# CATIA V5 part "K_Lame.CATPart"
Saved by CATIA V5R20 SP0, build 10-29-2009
Part number: Lame
Bounding box of the stored display mesh (mm): x -10.5 to -4.5, y 4 to 196, z -27 to -7
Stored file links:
  G:\Khaled_CFAO_2011\SIL\SIL_GR1\mneves\Khaled\CAD_CATIA_Modifie\K_Lame.CATPart
  G:\Khaled_CFAO_2011\SIL\SIL_GR1\mneves\Khaled\CAD_CATIA_Modifie\K_AssPince_A_Bois.CATProduct
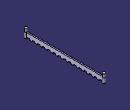
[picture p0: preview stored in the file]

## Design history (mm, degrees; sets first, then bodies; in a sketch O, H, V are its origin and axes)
External parameters (linked from other documents)
  External.Encombrement_Lame = 12 mm
  External.Epaisseur_Cloison = 3 mm
  External.Distance_Inter_Pivot = 200 mm
  External.Distance_Inter_Pivot.1 = 200 mm
  External.Encombrement_Lame.1 = 12 mm
Set1
  Plane1: linked copy from another document
  Point1: linked copy from another document
  Point2: linked copy from another document
  Line1: linked copy from another document
Body1 (main body)
  Sketch1 on Plane1, origin (0, 0, -27), H (1, 0, 0), V (0, 1, 0)
    arc A1 centre (-7.5, 193) radius 3 from (-6, 190.4019) to (-9, 190.4019) ccw
    point P1 (-7.5, 193)
    reference projected point E1 (-7.5, 193) from Point1
    arc A2 centre (-7.5, 7) radius 3 from (-9, 9.5981) to (-6, 9.5981) ccw
    point P2 (-7.5, 7)
    reference projected point E2 (-7.5, 7) from Point2
    line L1 (-6, 190.4019) -> (-6, 9.5981)
    line L2 (-9, 9.5981) -> (-9, 190.4019)
    reference projected line E3 (-7.5, 7) -> (-7.5, 193) from Line1
    reference projected line E4 (-7.5, 7) -> (-7.5, 193) from Line1
    radius A1 = 3 {= External.Encombrement_Lame /4}
    radius A2 = 3 {= External.Encombrement_Lame /4}
    distance E3 L2 = 1.5 {= External.Encombrement_Lame /8}
    distance L1 E4 = 1.5 {= External.Encombrement_Lame /8}
    coincidence: P1 E1, P2 E2
    vertical: L1 V, L2 V
  Pad1: profile Sketch1, direction (0, 0, 1), length 12 {= (External.Distance_Inter_Pivot.1 /8+External.Distance_Inter_Pivot.1 /40)/2-External.Epaisseur_Cloison}
  Sketch2 on end face of Pad1, origin (0, 0, -15), H (1, 0, 0), V (0, 1, 0)
    circle A1 centre (-7.5, 193) radius 3
    point P1 (-7.5, 193)
    circle A2 centre (-7.5, 7) radius 3
    point P2 (-7.5, 7)
    reference projected point E1 (-7.5, 7) from Point2
    reference projected point E2 (-7.5, 193) from Point1
    radius A1 = 3 {= External.Encombrement_Lame /4}
    radius A2 = 3 {= External.Encombrement_Lame /4}
    coincidence: P2 E1, P1 E2
  Pad2: profile Sketch2, direction (0, 0, 1), length 8 {= External.Distance_Inter_Pivot.1 /10-((External.Distance_Inter_Pivot /8+External.Distance_Inter_Pivot /40)/2-External.Epaisseur_Cloison )}
  Sketch3 on face of Pad1 from Sketch1.L1, origin (-6, 0, 0), H (0, 1, 0), V (0, 0, 1)
    line L1 (190, -27) -> (189, -24)
    line L2 (189, -24) -> (184, -24)
    line L3 (184, -24) -> (183, -27)
    horizontal: L2 H
  Pocket1: profile Sketch3, direction (-1, 0, 0), through (limit type 3)
  RectPattern1: of Pocket1, direction 1 instances 15, spacing 12.3, along face of Pad1 from Sketch1.L1 reversed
